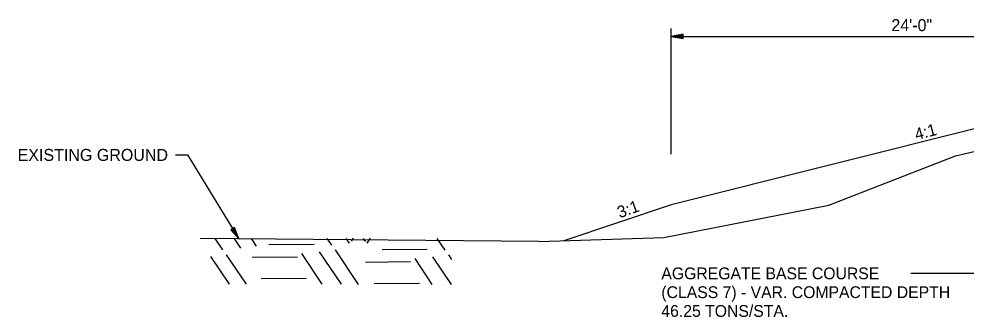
# Model space of a CAD drawing. Extents: x 1461846 to 1462006, y 1686171 to 1686805.
# Drawn here: x 1461858.38 to 1461905.82, y 1686235.88 to 1686250.79 of the extents above; entities that cross this region are included whole.
import ezdxf

# ---------------------------------------------------------------- set-up
doc = ezdxf.new("R2010")
doc.units = 0
for name, color, linetype in [('19', 7, 'Continuous'), ('42', 7, 'Continuous'), ('Level 9', 7, 'Continuous'), ('R_Draft', 7, 'Continuous')]:
    doc.layers.add(name, color=color, linetype=linetype)

msp = doc.modelspace()

# ---------------------------------------------------------------- linework, layer by layer
at = {"layer": '19'}
for p, q in [((1461891.646, 1686250.022), (1461891.046, 1686249.917)), ((1461891.046, 1686249.917), (1461891.646, 1686249.812)), ((1461891.646, 1686249.967), (1461891.206, 1686249.932)), ((1461891.206, 1686249.902), (1461891.646, 1686249.862)), ((1461891.646, 1686249.812), (1461891.646, 1686250.022)), ((1461884.415, 1686239.658), (1461867.458, 1686239.806)), ((1461868.595, 1686239.234), (1461868.215, 1686239.808)), ((1461869.491, 1686239.326), (1461869.159, 1686239.815)), ((1461870.285, 1686239.418), (1461870.023, 1686239.813)), ((1461873.162, 1686239.503), (1461870.901, 1686239.491)), ((1461874.049, 1686239.474), (1461873.824, 1686239.812)), ((1461874.945, 1686239.566), (1461874.779, 1686239.81)), ((1461875.035, 1686239.672), (1461875.141, 1686239.822)), ((1461875.739, 1686239.658), (1461875.634, 1686239.807)), ((1461875.829, 1686239.578), (1461875.996, 1686239.822)), ((1461879.725, 1686239.223), (1461879.333, 1686239.806)), ((1461869.777, 1686237.516), (1461868.781, 1686238.992)), ((1461873.577, 1686237.515), (1461872.545, 1686239.047)), ((1461874.533, 1686237.513), (1461873.44, 1686239.139)), ((1461875.387, 1686237.51), (1461874.235, 1686239.231)), ((1461878.836, 1686239.262), (1461876.576, 1686239.241)), ((1461880.065, 1686238.756), (1461879.911, 1686238.981)), ((1461868.923, 1686237.518), (1461867.986, 1686238.9)), ((1461872.332, 1686238.875), (1461870.061, 1686238.862)), ((1461877.996, 1686238.633), (1461875.737, 1686238.612)), ((1461879.087, 1686237.509), (1461878.221, 1686238.797)), ((1461880.042, 1686237.507), (1461879.116, 1686238.889)), ((1461903.064, 1686238.068), (1461907.262, 1686238.068)), ((1461872.774, 1686237.804), (1461870.514, 1686237.783)), ((1461878.449, 1686237.554), (1461876.178, 1686237.541))]:
    msp.add_line(p, q, dxfattribs=at)
at = {"layer": 'Level 9'}
for p, q in [((1461891.046, 1686244.031), (1461891.046, 1686250.32)), ((1461891.046, 1686249.917), (1461915.046, 1686249.917))]:
    msp.add_line(p, q, dxfattribs=at)
at = {"layer": 'R_Draft'}
for p, q in [((1461911.046, 1686246.488), (1461891.046, 1686241.488)), ((1461891.046, 1686241.488), (1461885.673, 1686239.697)), ((1461869.176, 1686240.356), (1461868.998, 1686240.246)), ((1461869.4, 1686239.789), (1461869.176, 1686240.356)), ((1461868.998, 1686240.246), (1461869.4, 1686239.789)), ((1461869.039, 1686240.268), (1461869.303, 1686239.919)), ((1461869.326, 1686239.93), (1461869.133, 1686240.324))]:
    msp.add_line(p, q, dxfattribs=at)
for points in [[(1461898.954, 1686241.476), (1461905.286, 1686243.936), (1461907.805, 1686244.527), (1461913.029, 1686245.425), (1461914.716, 1686245.68), (1461915.046, 1686246.481), (1461920.316, 1686246.387), (1461926.976, 1686246.462), (1461933.536, 1686246.367), (1461935.046, 1686246.521), (1461937.792, 1686245.91), (1461938.868, 1686245.881), (1461962.881, 1686248.455)], [(1461866.217, 1686243.988), (1461866.817, 1686243.988), (1461869.4, 1686239.789)], [(1461884.415, 1686239.658), (1461890.684, 1686239.851), (1461898.954, 1686241.476)]]:
    msp.add_lwpolyline(points, dxfattribs=at)

# ---------------------------------------------------------------- texts
at = {"layer": '19'}
for s, rotation, p in [('4:1', 14.9782, (1461903.337, 1686244.716)), ('3:1', 19.5057, (1461888.474, 1686240.816))]:
    msp.add_text(s, height=0.59, rotation=rotation, dxfattribs=at).set_placement(p)
for s, p in [('AGGREGATE BASE COURSE', (1461890.559, 1686237.765)), ('(CLASS 7) - VAR. COMPACTED DEPTH', (1461890.559, 1686236.825)), ('46.25 TONS/STA.', (1461890.559, 1686235.885))]:
    msp.add_text(s, height=0.59001, dxfattribs=at).set_placement(p)
at = {"layer": '42'}
msp.add_text('24\'-0"', height=0.6, dxfattribs=at).set_placement((1461902.081, 1686250.181))
at = {"layer": 'R_Draft'}
msp.add_text('EXISTING GROUND', height=0.6, dxfattribs=at).set_placement((1461858.315, 1686243.688))

doc.saveas('drawing.dxf')
